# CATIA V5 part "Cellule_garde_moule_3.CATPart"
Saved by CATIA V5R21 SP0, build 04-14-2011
Part number: Moule_cellule_garde.1
Bounding box of the stored display mesh (mm): x -18 to 18, y -72 to 72, z -15 to 0
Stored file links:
  C:\Users\zerma\Pictures\Moule_2\Cellule_garde_moule_3.CATPart
  Product1.CATProduct
  C:\Users\zerma\Pictures\Moule\Moule_v1.CATPart
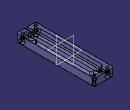
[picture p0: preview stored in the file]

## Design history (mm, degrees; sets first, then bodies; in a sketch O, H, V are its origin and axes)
Body1 (main body)
  Sketch1 on yz-plane, origin (0, 0, 0), H (0, 1, 0), V (0, 0, 1)
    line L1 (-95, -12.5) -> (95, -12.5)
    point P1 (-95, -12.5)
    line L2 (-100, -15) -> (100, -15)
    point P3 (-100, -15)
    line L3 (-95, -12.5) -> (-95, 0)
    point P5 (-95, 0)
    line L4 (-100, -15) -> (-100, 0)
    point P6 (-100, 0)
    line L5 (-95, 0) -> (-100, 0)
    point P7 (100, 0)
    point P8 (100, -15)
    line L6 (100, -15) -> (100, 0)
    point P9 (95, 0)
    line L7 (95, 0) -> (100, 0)
    point P10 (95, -12.5)
    line L8 (95, -12.5) -> (95, 0)
    distance L1 H = 12.5
    distance L1 L2 = 2.5
    length L4 = 15
    distance L4 L3 = 5
    length L1 = 190
    length L2 = 200
    distance V L3 = 95
    horizontal: L1 H, L2 H, L5 H
    vertical: L3 V, L4 V
    symmetry: P6 P7 V, P3 P8 V, L4 L6 V, P5 P9 V, L5 L7 V, P1 P10 V, L3 L8 V
  Shaft1: profile Sketch1, axis Sketch1.H, angle 360
  Sketch2 on face of Shaft1 from Sketch1.L4, origin (0, -100, 0), H (1, 0, 0), V (0, 0, 1)
    line L1 (-10, 2.5) -> (10, 2.5)
    line L2 (10, 2.5) -> (10, -2.5)
    line L3 (10, -2.5) -> (-10, -2.5)
    line L4 (-10, -2.5) -> (-10, 2.5)
    length L2 = 5
    length L1 = 20
    horizontal: L1 H, L3 H
    vertical: L2 V, L4 V
    symmetry: L3 L1 H, L4 L2 V
  Pad1: profile Sketch2, direction (0, -1, 0), length 15
  Sketch3 on face of Pad1 from Sketch2.L1, origin (0, 0, 2.5), H (1, 0, 0), V (0, 1, 0)
    circle A1 centre (0, -107.5) radius 2.5
    point P1 (0, -107.5)
    reference intersected line E1 (14.7902, -100) -> (-14.7902, -100) from face of Shaft1 from Sketch1.L4
    radius A1 = 2.5
    distance P1 E1 = 7.5
    coincidence: P1 V
  Pocket1: profile Sketch3, direction (0, 0, -1), length 5, mirrored extent
  Fillet1: radius 2, on edge [face of Pad1 from Sketch2.L4 | end face of Pad1]; edge [face of Pad1 from Sketch2.L1 | end face of Pad1]; edge [face of Pad1 from Sketch2.L3 | end face of Pad1]; edge [face of Pad1 from Sketch2.L2 | end face of Pad1]; edge [face of Pad1 from Sketch2.L2 | face of Pad1 from Sketch2.L3]; edge [face of Shaft1 from Sketch1.L4 | face of Pad1 from Sketch2.L3]; edge [face of Pad1 from Sketch2.L3 | face of Pad1 from Sketch2.L4]; edge [face of Pocket1 from Sketch3.A1 | face of Pad1 from Sketch2.L3]; edge [face of Pad1 from Sketch2.L4 | face of Pad1 from Sketch2.L1]; edge [face of Pad1 from Sketch2.L1 | face of Pad1 from Sketch2.L2]; edge [face of Shaft1 from Sketch1.L4 | face of Pad1 from Sketch2.L1]; edge [face of Shaft1 from Sketch1.L4 | face of Pad1 from Sketch2.L4]; edge [face of Shaft1 from Sketch1.L4 | face of Pad1 from Sketch2.L2]; face of Pad1 from Sketch2.L1
  Mirror1: of Pad1, Pocket1, Fillet1, about zx-plane
  Fillet2: radius 4, on edge [face of Shaft1 from Sketch1.L2 | face of Shaft1 from Sketch1.L6]; edge [face of Shaft1 from Sketch1.L4 | face of Shaft1 from Sketch1.L2]
Body2
  Sketch4 on xy-plane, origin (0, 0, 0), H (1, 0, 0), V (0, 1, 0)
    line L1 (18, 72) -> (18, -72)
    line L2 (18, -72) -> (-18, -72)
    line L3 (-18, -72) -> (-18, 72)
    line L4 (-18, 72) -> (18, 72)
    length L4 = 36
    length L1 = 144
    vertical: L1 V, L3 V
    horizontal: L2 H, L4 H
    equidistance: L1 L3 O, L2 L4 O
  Pad2: profile Sketch4, direction (0, 0, -1), length 15
  Body3
    Sketch5 on yz-plane, origin (0, 0, 0), H (0, 1, 0), V (0, 0, 1)
      line L1 (-55, -3.5) -> (55, -3.5)
      point P1 (-55, -3.5)
      point P2 (55, -3.5)
      line L2 (-60, -11.5) -> (60, -11.5)
      point P3 (-60, -11.5)
      point P4 (60, -11.5)
      line L3 (-55, -3.5) -> (-55, 0)
      point P5 (-55, 0)
      line L4 (-60, -11.5) -> (-60, -2.5)
      point P6 (-60, -2.5)
      point P7 (60, -2.5)
      point P8 (60, -11.5)
      line L5 (60, -11.5) -> (60, -2.5)
      point P9 (55, 0)
      point P10 (55, -3.5)
      line L6 (55, -3.5) -> (55, 0)
      line L7 (-60, -2.5) -> (-72, -2.5)
      line L8 (-72, -2.5) -> (-72, 0)
      line L9 (-72, 0) -> (-55, 0)
      point P13 (-55, 0)
      line L10 (60, -2.5) -> (67, -2.5)
      line L11 (67, -2.5) -> (67, 0)
      line L12 (67, 0) -> (55, 0)
      distance L1 H = 3.5
      distance L1 L2 = 8
      distance L4 L3 = 5
      distance V L3 = 55
      length L9 = 17
      length L12 = 12
      length L11 = 2.5
      horizontal: L1 H, L2 H, L7 H, L9 H, L10 H, L12 H
      vertical: L3 V, L4 V, L8 V, L11 V
      symmetry: P6 P7 V, P3 P8 V, L4 L5 V, P5 P9 V, P1 P10 V, L3 L6 V
      coincidence: P13 P5, L9 H, P4 P8, P2 P10
    Shaft2: profile Sketch5, axis Sketch5.H, angle 360
  Remove1: tool Body3
  Sketch6 on face of Shaft2 from Sketch5.L6, origin (0, 55, 0), H (-1, 0, 0), V (0, 0, 1)
    circle A1 centre (0, 0) radius 3.5
    reference projected circle E1 centre (0, 0) radius 3.5 from edge [face of Shaft2 from Sketch5.L1 | face of Shaft2 from Sketch5.L6]
    reference projected circle E2 centre (0, 0) radius 3.5 from edge [face of Shaft2 from Sketch5.L1 | face of Shaft2 from Sketch5.L6]
    coincidence: A1 E1
    concentricity: A1 E2
  Pocket2: profile Sketch6, direction (0, -1, 0), up to face of Shaft2 from Sketch5.L3
  Sketch7 on end face of Pad2, origin (0, 0, -15), H (1, 0, 0), V (0, -1, 0)
    circle A1 centre (12, 66) radius 2.25
    point P1 (12, 66)
    circle A2 centre (12, -66) radius 2.25
    circle A3 centre (-12, 66) radius 2.25
    circle A4 centre (-12, -66) radius 2.25
    reference projected line E1 (18, 123.5) -> (18, -123.5) from edge [end face of Pad2 | face of Pad2 from Sketch4.L1]
    reference projected line E2 (-25, 72) -> (25, 72) from edge [end face of Pad2 | face of Pad2 from Sketch4.L2]
    radius A1 = 2.25
    distance P1 E1 = 6
    distance P1 E2 = 6
    symmetry: A1 A2 H, A1 A3 V, A3 A4 H
  Pocket3: profile Sketch7, direction (0, 0, 1), length 50, mirrored extent
  Chamfer1: length 2, angle 45, on edge [end face of Pad2 | face of Pad2 from Sketch4.L2]; edge [end face of Pad2 | face of Pad2 from Sketch4.L3]; edge [end face of Pad2 | face of Pad2 from Sketch4.L4]; edge [end face of Pad2 | face of Pad2 from Sketch4.L1]; edge [face of Pad2 from Sketch4.L1 | face of Pad2 from Sketch4.L4]; edge [face of Pad2 from Sketch4.L4 | face of Pad2 from Sketch4.L3]; edge [face of Pad2 from Sketch4.L2 | face of Pad2 from Sketch4.L1]; edge [face of Pad2 from Sketch4.L3 | face of Pad2 from Sketch4.L2]
  Sketch8 on end face of Pad2, origin (0, 0, -15), H (1, 0, 0), V (0, -1, 0)
    circle A1 centre (12, 66) radius 3.5
    reference projected circle E1 centre (12, 66) radius 2.25 from edge [face of Pocket3 from Sketch7.A1 | end face of Pad2]
    circle A2 centre (12, -66) radius 3.5
    circle A3 centre (-12, 66) radius 3.5
    circle A4 centre (-12, -66) radius 3.5
    radius A1 = 3.5
    concentricity: A1 E1
    symmetry: A1 A2 H, A1 A3 V, A3 A4 H
  Pocket4: profile Sketch8, direction (0, 0, 1), length 8
  Fillet3: radius 4, on edge [face of Shaft2 from Sketch5.L5 | face of Shaft2 from Sketch5.L2]
  Fillet4: radius 4, on edge [face of Shaft2 from Sketch5.L2 | face of Shaft2 from Sketch5.L4]
  DatumCurve1
  Sketch9 on start face of Pad2, origin (0, 0, 0), H (1, 0, 0), V (0, 1, 0)
    circle A1 centre (0, 53) radius 1
    point P1 (0, 53)
    reference projected line E1 (28, 118) -> (28, -118) from edge of DatumCurve1
    reference projected line E2 (25, 72) -> (-25, 72) from edge [face of Pad2 from Sketch4.L4 | start face of Pad2]
    circle A2 centre (0, -53) radius 1
    radius A1 = 1
    distance P1 E1 = 28
    distance P1 E2 = 19
    symmetry: A1 A2 H
  Pocket5: profile Sketch9, direction (0, 0, -1), through (limit type 6)
  Sketch10 on face of Shaft2 from Sketch5.L4, origin (0, -60, 0), H (-1, 0, 0), V (0, 0, 1)
    circle A1 centre (0, -8) radius 2
    point P1 (0, -8)
    reference projected line E1 (11.5, 0) -> (2.5, 0) from edge [start face of Pad2 | face of Shaft2 from Sketch5.L4]
    radius A1 = 2
    distance P1 E1 = 8
  Pocket6: profile Sketch10, direction (0, -1, 0), length 13, mirrored extent
  CLDGeom1 "Maillage.1"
